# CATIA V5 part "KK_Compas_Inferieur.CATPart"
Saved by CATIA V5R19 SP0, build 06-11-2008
Part number: Compas inferieur
Bounding box of the stored display mesh (mm): x -122 to 122, y 1289.003 to 1661.6, z -2646.992 to -2262.39
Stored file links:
  G:\Khaled_CFAO_2011\ST2M\ST2M_GR2\aboulegue\Khaled\CAD_thinkMOTION\KK_Compas_Inferieur.CATPart
  G:\Khaled_CFAO_2011\ST2M\ST2M_GR2\aboulegue\Khaled\CAD_thinkMOTION\KK_Train_Atterrissage.CATProduct
  G:\Khaled_CFAO_2011\ST2M\ST2M_GR2\aboulegue\Khaled\CAD_thinkMOTION\KK_SqueletteCompas_Inferieur.CATPart
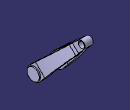
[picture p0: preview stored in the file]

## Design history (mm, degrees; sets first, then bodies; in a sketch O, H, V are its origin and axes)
Set1
  Plane1 "Plan compas inferieur 1": linked copy from another document
  Point1: linked copy from another document
  Point2: linked copy from another document
  Plane2 "Plan compas inferieur 2": linked copy from another document
  Line1 to Line3: linked copy from another document
Body1 (main body)
  Sketch1 on Plane2, origin (0, 1994.3381, -1914.5645), H (1, 0, 0), V (0, 0.6925, 0.7214)
    line L1 (0, -493.2078) -> (0, -589.2078)
    arc A1 centre (-193.1109, -589.2078) radius 193.1109 from (0, -589.2078) to (-20, -674.7907) cw
    point P4 (-20, -674.7907)
    arc A2 centre (360.844, -863.0732) radius 424.844 from (-20, -674.7907) to (-64, -863.0732) ccw
    line L2 (-64, -863.0732) -> (-64, -1003.0732)
    line L3 (-64, -1003.0732) -> (-112, -1003.0732)
    line L4 (-112, -1003.0732) -> (-112, -875.0732)
    arc A3 centre (391.7031, -875.0732) radius 503.7031 from (-112, -875.0732) to (-38.833, -613.6244) cw
    point P11 (-38.833, -613.6244)
    arc A4 centre (-79.0407, -589.2078) radius 47.0407 from (-38.833, -613.6244) to (-32, -589.2078) ccw
    line L5 (-32, -589.2078) -> (-32, -493.2078)
    line L6 (-32, -493.2078) -> (0, -493.2078)
    reference projected line E1 (0, -523.2078) -> (0, -939.0732) from Line2
    reference projected line E2 (0, -523.2078) -> (0, -939.0732) from Line2
    reference projected line E3 (-200, -939.0732) -> (200, -939.0732) from Line3
    reference projected line E4 (-200, -523.2078) -> (200, -523.2078) from Line1
    length L4 = 128
    length L2 = 140
    length L3 = 48
    length L5 = 96
    length L1 = 96
    length L6 = 32
    distance L2 E2 = 64
    distance L3 E3 = 64
    distance L6 E4 = 30
    distance P11 P4 = 64
    distance P4 L1 = 20
    vertical: L1 V, L2 V, L4 V
    tangency: A1 L1, A2 A1, A3 L4, A4 A3, L5 A4, L2 A2
    horizontal: L3 H, L6 H
    parallelism: L5 L4
    coincidence: L1 E1
  Sketch2 on Plane1, origin (0, 0, 0), H (0, 1, 0), V (0, 0, 1)
    line L1 (1611.93, -2270.2269) -> (1306.723, -2551.5596)
    arc A1 centre (1344, -2592) radius 55 from (1306.723, -2551.5596) to (1385.9276, -2627.596) ccw
    point P3 (1344, -2592)
    line L2 (1385.9276, -2627.596) -> (1654.5738, -2311.1649)
    arc A2 centre (1632, -2292) radius 29.612 from (1654.5738, -2311.1649) to (1611.93, -2270.2269) ccw
    point P6 (1632, -2292)
    reference projected point E1 (1344, -2592) from Point1
    reference projected point E2 (1632, -2292) from Point2
    angle L2 L1 = 7
    radius A1 = 55
    tangency: A1 L1, A2 L2, L1 A2, L2 A1
    coincidence: E1 P3, P6 E2
  SolidCombine1: FirstComponentProfile Sketch1, FirstComponentDirection Sketch1, SecondComponentProfile Sketch2, SecondComponentDirection Sketch2
  Sketch3 on face of SolidCombine1 from Sketch1.L1, origin (0, 0, 0), H (0, 1, 0), V (0, 0, 1)
    circle A1 centre (1632, -2292) radius 24
    point P1 (1632, -2292)
    reference projected point E1 (1632, -2292) from Point2
    radius A1 = 24
    coincidence: P1 E1
  Pocket1: profile Sketch3, direction (-1, 0, 0), through (limit type 6)
  Sketch4 on face of SolidCombine1 from Sketch1.L2, origin (-64, 0, 0), H (0, 1, 0), V (0, 0, 1)
    circle A1 centre (1344, -2592) radius 32
    point P1 (1344, -2592)
    reference projected point E1 (1344, -2592) from Point1
    radius A1 = 32
    coincidence: P1 E1
  Pocket2: profile Sketch4, direction (-1, 0, 0), through (limit type 6)
  Mirror1: of the body so far, about Plane1
  Sketch5 on face of Mirror1, origin (112, 0, 0), H (0, 1, 0), V (0, 0, 1)
    circle A1 centre (1344, -2592) radius 48
    reference projected arc E1 centre (1344, -2592) radius 55 from (1306.723, -2551.5596) to (1385.9276, -2627.596) ccw from edge [face of Mirror1 | face of Mirror1]
    radius A1 = 48
    concentricity: A1 E1
  Pad1: profile Sketch5, direction (1, 0, 0), length 10
  Sketch6 on start face of Pad1, origin (112, 0, 0), H (0, -1, 0), V (0, 0, 1)
    circle A1 centre (-1344, -2592) radius 32
    reference projected circle E1 centre (-1344, -2592) radius 32 from edge [start face of Pad1 | face of Mirror1]
    coincidence: E1 A1
  Pad2: profile Sketch6, direction (-1, 0, 0), length 234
